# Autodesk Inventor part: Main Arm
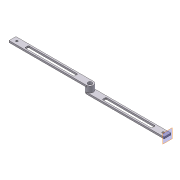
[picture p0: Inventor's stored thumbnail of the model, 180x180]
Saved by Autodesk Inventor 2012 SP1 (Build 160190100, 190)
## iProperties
Created: 2006-09
Part Number: Main Arm
Document SubType Name: Modeling
Material: Aluminum-6061
Mass: 43.4455 g
Surface Area: 135.175 cm^2
Volume: 16.0315 cm^3
Density: 2.71 g/cm^3
MajorVersion: 11
MinorVersion: 1
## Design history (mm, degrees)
sketch "Sketch1"
  geometry: L1 (-207, 0)-(276, 0) reference; L2 (-170, 0)-(170, 0); C1 r 8 at (0, 0); C2 r 2.5 at (-170, 0); C3 r 2.5 at (170, 0); 1 further point
  constraints: 3 centre point, 2 end point, 2 point on line, 1 coincident, 1 collinear, 1 equal radius
  dimensions: "d0" = 16 diameter of C1; "d1" = 170 distance of L2.end point (0, 0); "d2" = 170 distance of L2.start point (0, 0); "d3" = 5 diameter of C2
sketch "Sketch2"
  geometry: L1 (-180, -7)-(0, -7); L2 (-234, 0)-(18, 0) reference; L3 (0, -7.7)-(0, 2.1) reference; 2 further points
  constraints: 2 end point, 1 horizontal, 1 point on line
  dimensions: "d6" = 7 distance between parallel lines of L1 L2; "d9" = 10 horizontal distance of L1.start point (-170, 0)
workplane "Work Plane5"
sketch "Sketch5"
  geometry: L1 (-8, 2)-(8, 2); L2 (8, 2)-(8, -2); L3 (8, -2)-(-8, -2); L4 (-8, -2)-(-8, 2); L5 (-8, 2)-(8, -2); 3 further points
  constraints: 10 end point, 2 parallel, 1 coincident, 1 horizontal, 1 midpoint, 1 perpendicular
  dimensions: "d21" = 16 distance of L1.start L1.end; "d22" = 4 distance of L3.end L1.start
sweep "Sweep5" sketch "Sketch5" dims "d23" = 0
sketch "Sketch6"
  geometry: 3 further points
  constraints: 1 coincident, 1 vertical alignment, 2 other
extrude "Extrusion3" join sketch "Sketch6" stored distance "d32" = 20; taper "d33" = 0 deg
extrude "Extrusion4" cut sketch "Sketch1" stored distance "d34" = 20; taper "d35" = 0 deg
pattern_circular "Circular Pattern2" dims "d30" = 360 deg
sketch "Sketch10"
  geometry: L1 (180, 20.8)-(180, -1.6) reference; L2 (-36, 8)-(468, 8) reference; L3 (34.5, 12.5)-(145.5, 12.5); L4 (147.5, 10.5)-(147.5, 5.5); L5 (145.5, 3.5)-(34.5, 3.5); L6 (32.5, 5.5)-(32.5, 10.5); L7 (32.5, 12.5)-(147.5, 3.5); L8 (212.5, 10.5)-(212.5, 5.5); L9 (325.5, 12.5)-(214.5, 12.5); L10 (214.5, 3.5)-(325.5, 3.5); L11 (327.5, 12.5)-(212.5, 3.5); L12 (327.5, 5.5)-(327.5, 10.5); L13 (90, 12.5)-(90, 3.5); L14 (270, 12.5)-(270, 3.5); L15 (86, 12.5)-(86, 3.5); L16 (94, 12.5)-(94, 3.5); L17 (266, 12.5)-(266, 3.5); L18 (274, 12.5)-(274, 3.5); A1 r 2 centre (34.5, 10.5) between (34.5, 12.5) and (32.5, 10.5); A2 r 2 centre (34.5, 5.5) between (32.5, 5.5) and (34.5, 3.5); A3 r 2 centre (145.5, 5.5) between (145.5, 3.5) and (147.5, 5.5); A4 r 2 centre (145.5, 10.5) between (147.5, 10.5) and (145.5, 12.5); A5 r 2 centre (214.5, 5.5) between (212.5, 5.5) and (214.5, 3.5); A6 r 2 centre (214.5, 10.5) between (214.5, 12.5) and (212.5, 10.5); A7 r 2 centre (325.5, 10.5) between (327.5, 10.5) and (325.5, 12.5); A8 r 2 centre (325.5, 5.5) between (325.5, 3.5) and (327.5, 5.5); 7 further points
  constraints: 32 end point, 25 point on line, 17 symmetric about line, 16 point on circle, 8 centre point, 8 tangent, 5 midpoint, 4 perpendicular, 3 equal radius, 3 parallel, 1 horizontal, 6 other
  dimensions: "d52" = 9 distance of point (32.5, 3.5) L7.start; "d53" = 115 distance of L7.start point (147.5, 12.5); "d54" = 90 distance of point (90, 8) point (180, 8); "d55" = 2 radius of A1; "d541" = 8 distance between parallel lines of L15 L16; "d542" = 8 distance between parallel lines of L18 L17 (= d541)
extrude "Extrusion8" cut sketch "Sketch10" stored distance "d56" = 10; taper "d57" = 0 deg
sketch "Sketch11"
  geometry: C1 r 5 at (180, 8); 1 further point
  constraints: 1 centre point, 1 coincident
  dimensions: "d58" = 10 diameter of C1
extrude "Extrusion9" cut sketch "Sketch11" stored distance "d59" = 10; taper "d60" = 0 deg
extrude "Extrusion10" join sketch "Sketch10" stored distance "d543" = 10; taper "d544" = 0 deg
extrude "Extrusion11" join sketch "Sketch10" stored distance "d545" = 10; taper "d546" = 0 deg
fillet "Fillet2" dims "d547" = 2
body "Solid1"
other parameters: "sa_eq_min" = 14935.5, "sa_eq_max" = 4.42009e+07, "sa_pmax_min" = -2425870, "sa_pmax_max" = 4.5208e+07, "sa_pmin_min" = -4.46428e+07, "sa_pmin_max" = 2889300, "sa_d_min" = 0.00006, "sa_d_max" = 7.2767, "sa_sf_min" = 6.22159, "d100" = 4.18879, "d119" = 9809.999, "d120" = 4.18879, "d139" = 9809.999, "d140" = 4.18879, "d159" = 9809.999, "d160" = 4.18879, "d179" = 9809.999, "d180" = 4.18879, "d200" = 4.18879, "d219" = 9810.005, "d220" = 4.18879, "d239" = 9809.996, "d240" = 4.18879, "d259" = 9809.999, "d260" = 4.18879, "d279" = 9809.999, "d280" = 4.18879, "d299" = 9809.999, "d300" = 4.18879, "d319" = 9809.999, "d320" = 4.18879, "d339" = 9809.999, "d340" = 4.18879, "d359" = 9809.998, "d360" = 4.18879, "d379" = 9809.999, "d380" = 4.18879, "d399" = 9809.999, "d400" = 4.18879, "d419" = 9809.998, "d420" = 4.18879, "d440" = 4.18879, "d460" = 4.18879, "d480" = 4.18879, "d500" = 4.18879, "d520" = 4.18879, "d540" = 4.18879, "d567" = 4.18879
